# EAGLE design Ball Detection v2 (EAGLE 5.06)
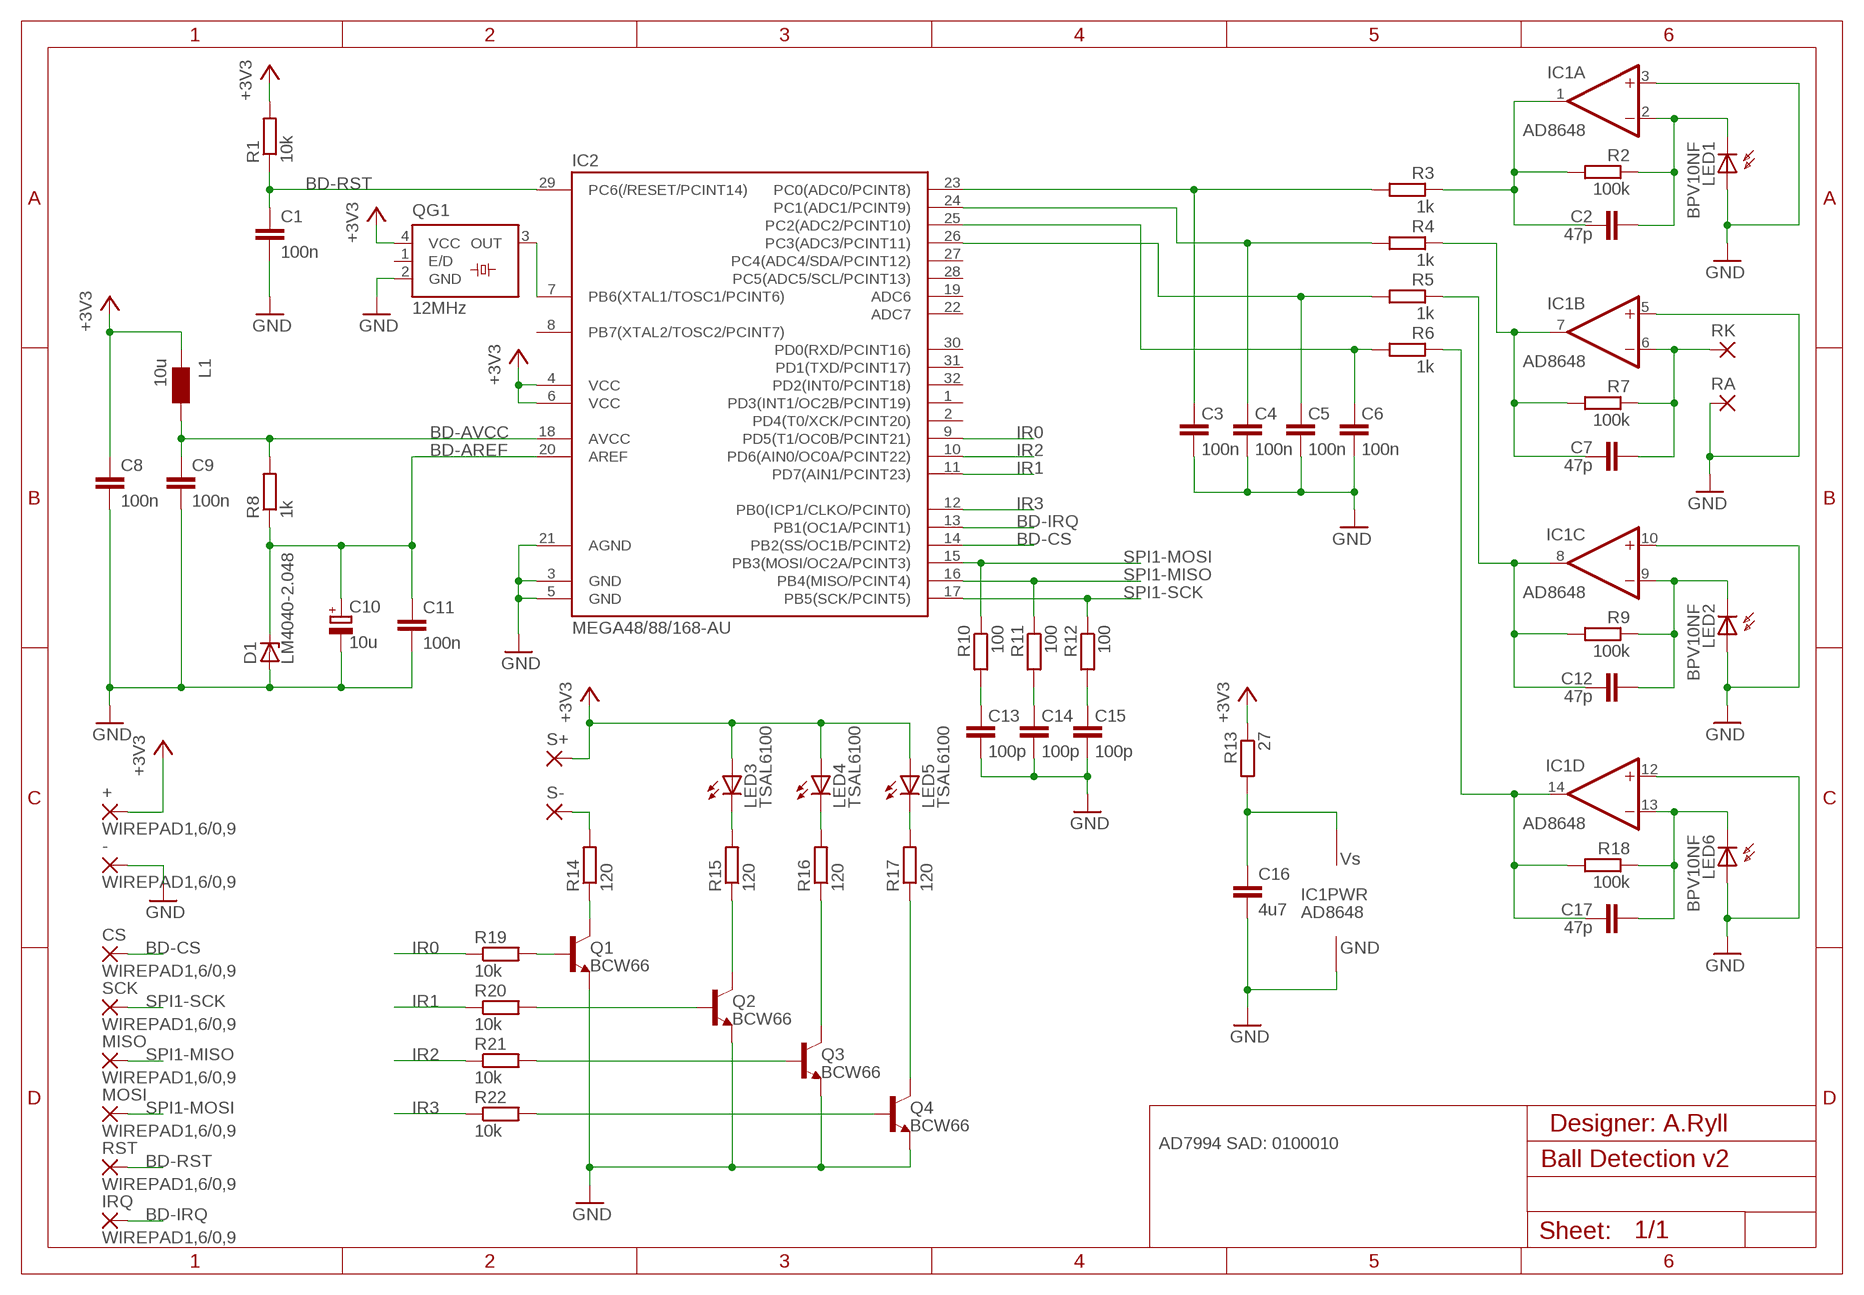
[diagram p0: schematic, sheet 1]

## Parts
+  WIREPAD1,6/0,9  [1,6/0,9]
-  WIREPAD1,6/0,9  [1,6/0,9]
C1  100n  C-EUC0805  [C0805]
C2  47p  C-EUC0805  [C0805]
C3  100n  C-EUC0805  [C0805]
C4  100n  C-EUC0805  [C0805]
C5  100n  C-EUC0805  [C0805]
C6  100n  C-EUC0805  [C0805]
C7  47p  C-EUC0805  [C0805]
C8  100n  C-EUC0805  [C0805]
C9  100n  C-EUC0805  [C0805]
C10  10u  CPOL-EUC/6032-28W  [C/6032-28W]
C11  100n  C-EUC0805  [C0805]
C12  47p  C-EUC0805  [C0805]
C13  100p  C-EUC0805  [C0805]
C14  100p  C-EUC0805  [C0805]
C15  100p  C-EUC0805  [C0805]
C16  4u7  C-EUC0805  [C0805]
C17  47p  C-EUC0805  [C0805]
CS  WIREPAD1,6/0,9  [1,6/0,9]
D1  LM4040-2.048  ZENER-DIODELM4040  [SOT23]
IC1  AD8648  [TSSOP14]
IC2  MEGA48/88/168-AU  [TQFP32-08]
IRQ  WIREPAD1,6/0,9  [1,6/0,9]
L1  10u  WE-MI_0805  [0805]
LED1  BPV10NF  PHOTO-LED  [LED5MM]
LED2  BPV10NF  PHOTO-LED  [LED5MM]
LED3  TSAL6100  LED5MM  [LED5MM]
LED4  TSAL6100  LED5MM  [LED5MM]
LED5  TSAL6100  LED5MM  [LED5MM]
LED6  BPV10NF  PHOTO-LED  [LED5MM]
MISO  WIREPAD1,6/0,9  [1,6/0,9]
MOSI  WIREPAD1,6/0,9  [1,6/0,9]
Q1  BCW66  BCW60SMD  [SOT23-BEC]
Q2  BCW66  BCW60SMD  [SOT23-BEC]
Q3  BCW66  BCW60SMD  [SOT23-BEC]
Q4  BCW66  BCW60SMD  [SOT23-BEC]
QG1  12MHz  SM77H  [SM77H]
R1  10k  R-EU_R0805  [R0805]
R2  100k  R-EU_R0805  [R0805]
R3  1k  R-EU_R0805  [R0805]
R4  1k  R-EU_R0805  [R0805]
R5  1k  R-EU_R0805  [R0805]
R6  1k  R-EU_R0805  [R0805]
R7  100k  R-EU_R0805  [R0805]
R8  1k  R-EU_R0805  [R0805]
R9  100k  R-EU_R0805  [R0805]
R10  100  R-EU_R0805  [R0805]
R11  100  R-EU_R0805  [R0805]
R12  100  R-EU_R0805  [R0805]
R13  27  R-EU_R0805  [R0805]
R14  120  R-EU_R0805  [R0805]
R15  120  R-EU_R0805  [R0805]
R16  120  R-EU_R0805  [R0805]
R17  120  R-EU_R0805  [R0805]
R18  100k  R-EU_R0805  [R0805]
R19  10k  R-EU_R0805  [R0805]
R20  10k  R-EU_R0805  [R0805]
R21  10k  R-EU_R0805  [R0805]
R22  10k  R-EU_R0805  [R0805]
RA  WIREPAD1,6/0,9  [1,6/0,9]
RK  WIREPAD1,6/0,9  [1,6/0,9]
RST  WIREPAD1,6/0,9  [1,6/0,9]
S+  WIREPAD1,6/0,9  [1,6/0,9]
S-  WIREPAD1,6/0,9  [1,6/0,9]
SCK  WIREPAD1,6/0,9  [1,6/0,9]

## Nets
+3V3: +.1(P) C8.1 IC2.4(VCC) IC2.6(VCC) L1.1 LED3.A LED4.A LED5.A QG1.4(VCC) R1.2 R13.1 S+.1(P)
AI0: C3.2 IC2.23(PC0(ADC0/PCINT8)) R3.2
AI1: C4.2 IC2.24(PC1(ADC1/PCINT9)) R4.2
AI2: C5.2 IC2.26(PC3(ADC3/PCINT11)) R5.2
AI3: C6.2 IC2.25(PC2(ADC2/PCINT10)) R6.2
BD-AREF: C10.+ C11.1 D1.1(C) IC2.20(AREF) R8.1
BD-AVCC: C9.1 IC2.18(AVCC) L1.2 R8.2
BD-CS: CS.1(P) IC2.14(PB2(SS/OC1B/PCINT2))
BD-IRQ: IC2.13(PB1(OC1A/PCINT1)) IRQ.1(P)
BD-RST: C1.1 IC2.29(PC6(/RESET/PCINT14)) R1.1 RST.1(P)
GND: -.1(P) C1.2 C3.1 C4.1 C5.1 C6.1 C8.2 C9.2 C10.- C11.2 C13.1 C14.1 C15.1 C16.2 D1.2(A) IC1.3(A:+IN) IC1.5(B:+IN) IC1.10(C:+IN) IC1.11(PWR:GND) IC1.12(D:+IN) IC2.3(GND) IC2.5(GND) IC2.21(AGND) LED1.A LED2.A LED6.A Q1.E Q2.E Q3.E Q4.E QG1.2(GND) RA.1(P)
IR0: IC2.9(PD5(T1/OC0B/PCINT21)) R19.1
IR1: IC2.11(PD7(AIN1/PCINT23)) R20.1
IR2: IC2.10(PD6(AIN0/OC0A/PCINT22)) R21.1
IR3: IC2.12(PB0(ICP1/CLKO/PCINT0)) R22.1
N$1: C2.2 IC1.1(A:OUT) R2.2 R3.1
N$2: C15.2 R12.2
N$3: C14.2 R11.2
N$4: C7.2 IC1.7(B:OUT) R4.1 R7.2
N$5: C12.2 IC1.8(C:OUT) R5.1 R9.2
N$6: C17.2 IC1.14(D:OUT) R6.1 R18.2
N$7: C13.2 R10.2
N$103: R14.2 S-.1(P)
N$104: LED3.K(C) R15.2
N$115: LED5.K(C) R17.2
N$116: LED4.K(C) R16.2
N$117: Q1.B R19.2
N$119: C2.1 IC1.2(A:-IN) LED1.K(C) R2.1
N$121: Q2.B R20.2
N$122: C7.1 IC1.6(B:-IN) R7.1 RK.1(P)
N$123: Q3.B R21.2
N$124: C12.1 IC1.9(C:-IN) LED2.K(C) R9.1
N$125: Q4.B R22.2
N$126: C17.1 IC1.13(D:-IN) LED6.K(C) R18.1
N$127: Q1.C R14.1
N$128: Q2.C R15.1
N$129: Q3.C R16.1
N$146: Q4.C R17.1
SPI1-MISO: IC2.16(PB4(MISO/PCINT4)) MISO.1(P) R11.1
SPI1-MOSI: IC2.15(PB3(MOSI/OC2A/PCINT3)) MOSI.1(P) R10.1
SPI1-SCK: IC2.17(PB5(SCK/PCINT5)) R12.1 SCK.1(P)
VOP: C16.1 IC1.4(PWR:VS) R13.2
XTAL: IC2.7(PB6(XTAL1/TOSC1/PCINT6)) QG1.3(OUT)
Unconnected: IC2.1(PD3(INT1/OC2B/PCINT19)) IC2.2(PD4(T0/XCK/PCINT20)) IC2.8(PB7(XTAL2/TOSC2/PCINT7)) IC2.19(ADC6) IC2.22(ADC7) IC2.27(PC4(ADC4/SDA/PCINT12)) IC2.28(PC5(ADC5/SCL/PCINT13)) IC2.30(PD0(RXD/PCINT16)) IC2.31(PD1(TXD/PCINT17)) IC2.32(PD2(INT0/PCINT18)) QG1.1(E/D)

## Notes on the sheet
- Designer: A.Ryll
- AD7994 SAD: 0100010

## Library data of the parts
+ - CS IRQ MISO MOSI RA RK RST S+ S- SCK = wirepad:WIREPAD: Wire PAD connect wire on PCB
C1-C9 C11-C17 = rcl:C-EU: CAPACITOR, European symbol
C10 = rcl:CPOL-EU: POLARIZED CAPACITOR, European symbol
D1 = Marvin:ZENER-DIODE: Z-Diode
IC1 = Marvin:AD8648
IC2 = avr-6:MEGA48/88/168
L1 = wuerth-elektronik:WE-MI: SMD Multilayer Inductor WE-MI
LED1 LED2 LED6 = Marvin:PHOTO-LED
LED3-LED5 = led:LED: LED
Q1-Q4 = transistor-npn:BCW60*: NPN Transistor
QG1 = crystal:SM77H: 3.3V CMOS Clock Oscillator Source: www.pletronics.com .. sm77h%203.3v.pdf
R1-R22 = rcl:R-EU_: RESISTOR, European symbol

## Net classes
0 default: width 0.152 mm, clearance 0.152 mm

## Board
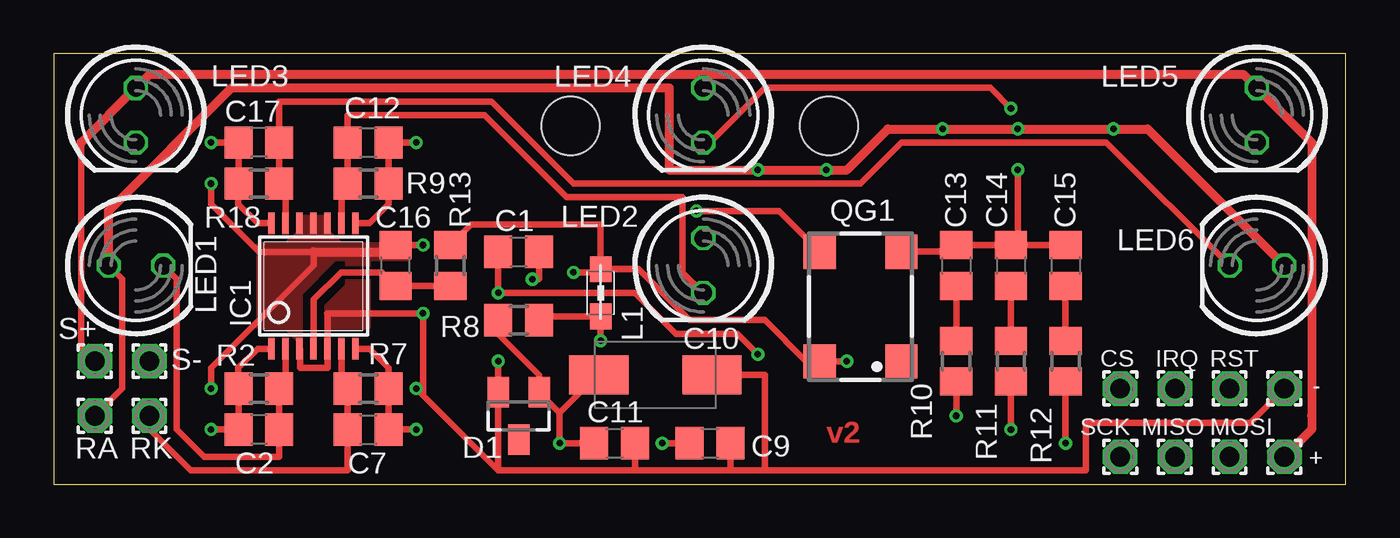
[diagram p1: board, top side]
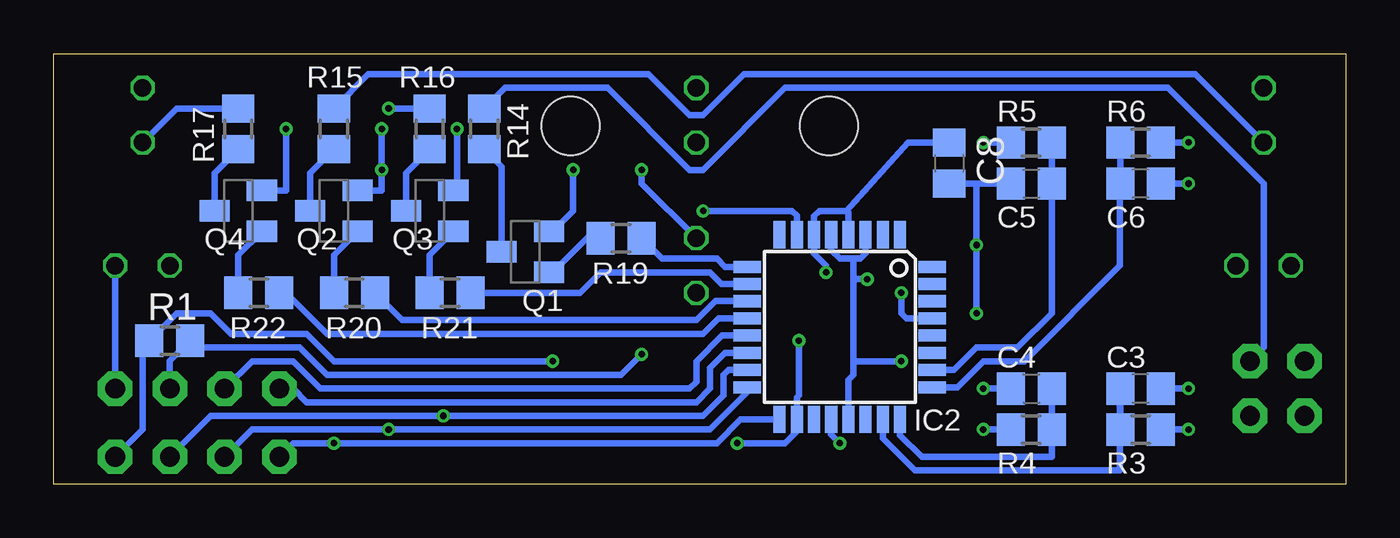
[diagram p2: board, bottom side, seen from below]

Size 60 x 20 mm. Coordinates in mm from the lower left corner, seen from the top.
Outline: 0,0 60,0 60,20 0,20 0,0
Copper layers (1*16): Top 0.035mm / dielectric 1.5mm / Bottom 0.035mm
Design rules "std *": minimum track width 10mil, minimum drill 0.3mm, track to track 0.15mm, track to pad 0.15mm, pad to pad 0.15mm, via to via 0.15mm, smd to smd 0.15mm, copper to edge 0.15mm, drill to drill 0.2mm, minimum pad ring 6mil, minimum via ring 6mil, stop-mask expansion 4mil, vias tented up to drill 0mil, thermal gap 10mil
Holes 2.7 mm at 24,16.65 36,16.65
bKeepout: area 21.6,12.7 to 38.1,19.7

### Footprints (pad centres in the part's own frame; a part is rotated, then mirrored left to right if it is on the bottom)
1,6/0,9 = drill 0.914 pad 1.6 octagon: 1 0,0
C0805 = smd 1.3 x 1.5: 1 -0.95,0; 2 0.95,0
C/6032-28W = smd 2.75 x 1.8: + 2.625,0; - -2.625,0
SOT23 = smd 1 x 1.4: 1 -0.95,-1.1; 2 0.95,-1.1; 3 0,1.1
TSSOP14 = smd 0.305 x 0.991: 1 -1.95,-2.918; 2 -1.3,-2.918; 3 -0.65,-2.918; 4 0,-2.918; 5 0.65,-2.918; 6 1.3,-2.918; 7 1.95,-2.918; 8 1.95,2.918; 9 1.3,2.918; 10 0.65,2.918; 11 0,2.918; 12 -0.65,2.918; 13 -1.3,2.918; 14 -1.95,2.918
TQFP32-08 = smd 1.27 x 0.559: 1 -4.293,2.8; 2 -4.293,2; 3 -4.293,1.2; 4 -4.293,0.4; 5 -4.293,-0.4; 6 -4.293,-1.2; 7 -4.293,-2; 8 -4.293,-2.8; 17 4.293,-2.8; 18 4.293,-2; 19 4.293,-1.2; 20 4.293,-0.4; 21 4.293,0.4; 22 4.293,1.2; 23 4.293,2; 24 4.293,2.8 | smd 0.559 x 1.27: 9 -2.8,-4.293; 10 -2,-4.293; 11 -1.2,-4.293; 12 -0.4,-4.293; 13 0.4,-4.293; 14 1.2,-4.293; 15 2,-4.293; 16 2.8,-4.293; 25 2.8,4.293; 26 2,4.293; 27 1.2,4.293; 28 0.4,4.293; 29 -0.4,4.293; 30 -1.2,4.293; 31 -2,4.293; 32 -2.8,4.293
0805 = smd 1.2 x 1: 1 -1.1,0; 2 1.1,0
LED5MM = drill 0.813 octagon: A -1.27,0; K 1.27,0
SOT23-BEC = smd 1 x 1.4: B -0.95,-1.1; C 0,1.1; E 0.95,-1.1
SM77H = smd 1.6 x 1.5: 1 -2.55,-1.9; 2 2.55,-1.9; 3 2.55,1.9; 4 -2.55,1.9
R0805 = smd 1.3 x 1.5: 1 -0.95,0; 2 0.95,0

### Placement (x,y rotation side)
+  57.15,1.27 0 top
-  57.15,4.45 0 top
C1  21.59,10.79 0 top
C2  9.53,2.54 180 top
C3  9.53,4.45 180 bottom
C4  14.61,4.45 0 bottom
C5  14.61,13.97 0 bottom
C6  9.53,13.97 180 bottom
C7  14.61,2.54 0 top
C8  18.41,14.92 270 bottom
C9  30.48,1.91 0 top
C10  27.94,5.08 180 top
C11  26.04,1.91 0 top
C12  14.61,15.88 0 top
C13  41.91,10.16 270 top
C14  44.45,10.16 270 top
C15  46.99,10.16 270 top
C16  15.88,10.16 90 top
C17  9.53,15.88 180 top
CS  49.53,4.45 0 top
D1  21.59,3.17 180 top
IC1  12.06,9.21 0 top
IC2  23.5,7.3 270 bottom
IRQ  52.07,4.45 0 top
L1  25.4,8.89 270 top
LED1  3.81,10.16 0 top
LED2  30.16,10.16 270 top
LED3  3.81,17.14 270 top
LED4  30.16,17.14 270 top
LED5  55.88,17.14 270 top
LED6  55.88,10.16 180 top
MISO  52.07,1.27 0 top
MOSI  54.61,1.27 0 top
Q1  38.1,10.79 90 bottom
Q2  46.99,12.7 90 bottom
Q3  42.55,12.7 90 bottom
Q4  51.44,12.7 90 bottom
QG1  37.47,8.26 90 top
R1  54.61,6.67 180 bottom
R2  9.53,4.45 180 top
R3  9.53,2.54 180 bottom
R4  14.61,2.54 0 bottom
R5  14.61,15.88 0 bottom
R6  9.53,15.88 180 bottom
R7  14.61,4.45 0 top
R8  21.59,7.62 0 top
R9  14.61,13.97 0 top
R10  41.91,5.71 90 top
R11  44.45,5.71 90 top
R12  46.99,5.71 90 top
R13  18.41,10.16 270 top
R14  40.01,16.51 90 bottom
R15  46.99,16.51 90 bottom
R16  42.55,16.51 90 bottom
R17  51.44,16.51 90 bottom
R18  9.53,13.97 180 top
R19  33.66,11.43 180 bottom
R20  46.04,8.89 180 bottom
R21  41.59,8.89 180 bottom
R22  50.48,8.89 180 bottom
RA  1.91,3.17 0 top
RK  4.45,3.17 0 top
RST  54.61,4.45 0 top
S+  1.91,5.71 0 top
S-  4.45,5.71 0 top
SCK  49.53,1.27 0 top

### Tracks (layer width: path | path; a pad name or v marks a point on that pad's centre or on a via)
+3V3  (via drill 0.3)
  Top 0.305: 1.27,15.88 1.27,6.35 S+.1 | v24.13,9.84 25.25,9.84 L1.1 | L1.1 25.4,12.06 19.37,12.06 R13.1 | L1.1 27.16,9.99 29.53,7.62 33.02,7.62 34.94,5.71 QG1.4 v36.83,5.71
  Top 0.406: 30.16,19.05 4.45,19.05 LED3.A 1.27,15.88 | 30.16,19.05 LED4.A | 30.16,19.05 55.24,19.05 LED5.A 58.42,15.88 58.42,3.17 58.42,2.54 +.1
  Bottom 0.305: IC2.4 23.09,12.62 23.18,12.7 | 23.18,12.7 24.45,12.7 24.7,12.45 IC2.6 24.7,10.72 24.13,10.16 v24.13,9.84 | C8.1 20.32,15.87 23.18,12.7 | +.1 55.88,2.54 55.88,6.67 55.56,6.99 R1.2 54.29,7.94 52.7,7.94 51.75,6.99 48.26,6.99 46.99,5.71 v36.83,5.71
AI0
  Bottom 0.305: R3.2 C3.2 10.48,0.64 20,0.64 21.5,2.13 IC2.23
AI1
  Bottom 0.305: C4.2 R4.2 13.65,1.27 19.68,1.27 20.7,2.28 IC2.24
AI2
  Bottom 0.305: R5.2 C5.2 13.65,7.94 15.24,6.35 17.14,6.35 18.19,5.3 IC2.26
AI3
  Bottom 0.305: R6.2 C6.2 10.48,10.16 14.92,5.71 16.83,5.71 18.04,4.5 IC2.25
BD-AREF  (via drill 0.3)
  Top 0.305: C11.1 v23.5,1.91 23.5,3.32 | 23.5,3.32 D1.1 22.54,5.08 20.64,6.98 R8.1 | C10.+ 25.25,5.08 23.5,3.32
  Bottom 0.305: IC2.20 23.89,2.31 v23.5,1.91
BD-AVCC  (via drill 0.3)
  Top 0.305: v28.26,1.91 C9.1 | v25.4,6.67 L1.2 22.71,7.79 R8.2
  Bottom 0.305: v28.26,1.91 26.04,1.91 25.5,2.44 IC2.18 25.5,4.03 25.4,4.13 v25.4,6.67
BD-CS
  Bottom 0.305: IC2.14 28.82,6.1 29.53,5.4 29.53,4.45 30.16,3.81 48.26,3.81 48.9,4.45 CS.1
BD-IRQ
  Bottom 0.305: IC2.13 28.98,6.9 30.16,5.71 30.16,4.76 30.48,4.45 47.62,4.45 48.9,5.71 50.8,5.71 IRQ.1
BD-RST  (via drill 0.3)
  Top 0.305: C1.1 v20.64,8.89 26.99,8.89 28.89,6.99 31.75,6.99 v32.7,6.03
  Bottom 0.305: RST.1 54.61,5.72 R1.1 53.66,6.35 48.58,6.35 47.31,5.08 33.66,5.08 v32.7,6.03 | IC2.29 20.4,7.7 20.64,7.94 v20.64,8.89
GND  (via drill 0.3)
  Top 0.305: v7.3,13.97 7.3,13.02 9.53,10.79 12.06,10.79 | 12.06,10.79 | v7.3,4.45 7.3,5.4 12.06,10.16 12.06,10.79 | 12.06,10.79 | IC1.3 11.43,6.28 11.43,5.4 12.7,5.4 12.71,5.41 IC1.5 12.71,7.92 12.7,7.94 v17.14,7.94 17.14,4.13 17.62,3.65 | RA.1 3.17,4.45 3.17,9.53 LED1.A | C14.1 C13.1 41.6,10.8 QG1.2 | C14.1 C15.1 | C14.1 44.77,11.43 44.77,14.29 v44.77,14.61 | 17.62,3.65 v16.83,4.45 | 17.62,3.65 20.64,0.64 20.95,0.64 | C16.2 v17.14,11.11 | v20.64,5.71 D1.2 20.64,0.64 20.95,0.64 | -.1 55.56,2.86 47.94,2.86 47.94,0.64 33.02,0.64 | 33.02,0.64 31.43,0.64 | 31.43,0.64 26.99,0.64 | 26.99,0.64 20.95,0.64 | C11.2 26.99,0.64 | C9.2 31.43,0.64 | C10.- 33.02,5.08 33.02,0.64 | C1.2 22.54,9.53 v22.23,9.53
  Top 0.406: LED6.A 50.8,16.51 v49.21,16.51 v44.77,16.51 v41.27,16.51 38.73,16.51 36.83,14.61 v35.88,14.61 v32.7,14.61 28.57,14.61 28.57,18.41 8.26,18.41 2.54,12.7 LED1.A | 12.06,10.79 16.19,10.79
  Bottom 0.305: Q3.E 41.28,13.65 v41.27,16.51 | Q2.E 44.77,13.65 v44.77,14.61 | v44.77,16.51 44.77,15.24 | 44.77,15.24 v44.77,14.61 | Q4.E 49.22,13.65 v49.21,16.51 | Q1.E 36.83,11.75 35.88,12.7 35.88,13.02 v35.88,14.61 | LED2.A 32.7,13.97 v32.7,14.61 | IC2.3 22.3,10.72 22.54,10.48 22.86,10.48 | 22.86,10.48 23.5,10.48 23.89,10.88 IC2.5 | IC2.21 23.09,4.84 22.86,5.08 22.86,5.71 | 22.86,5.71 22.86,9.53 | 22.86,9.53 22.86,10.48 | LED6.A -.1 | v44.77,14.61 44.77,15.24 | v16.83,4.45 C4.1 | v7.3,4.45 C3.1 | v7.3,13.97 C6.1 | 16.83,13.97 C5.1 | 16.83,13.97 C8.2 | 16.83,13.97 17.14,13.97 v17.14,11.11 v17.14,7.94 | v20.64,5.71 22.86,5.71 | 22.86,9.53 v22.23,9.53
  pour Top (no thermals): 16.51,11.11 13.34,11.11 12.7,11.75 12.7,12.38 11.43,12.38 11.43,11.75 10.79,11.11 9.53,11.11 9.53,7.3 10.79,7.3 11.43,6.67 11.43,8.89 13.02,10.48 16.51,10.48
  pour Top (no thermals): 13.65,10.48 13.65,9.21 12.7,8.26 12.7,7.3 14.61,7.3 14.61,10.48
IR0
  Bottom 0.305: IC2.9 28.84,10.1 29.21,10.48 31.75,10.48 R19.1
IR1
  Bottom 0.305: IC2.11 29.28,8.5 30.16,7.62 43.82,7.62 R20.1
IR2
  Bottom 0.305: IC2.10 28.99,9.3 29.53,9.84 34.61,9.84 35.56,8.89 R21.1
IR3
  Bottom 0.305: IC2.12 29.13,7.7 29.84,6.99 47.31,6.99 49.21,8.89 R22.1
N$1  (via drill 0.3)
  Top 0.305: IC1.1 9.46,6.29 8.57,5.4 R2.2 C2.2 | C2.2 v7.3,2.54 C2.2
  Bottom 0.305: v7.3,2.54 C2.2
N$2
  Top 0.305: R12.2 C15.2
N$3
  Top 0.305: R11.2 C14.2
N$4  (via drill 0.3)
  Top 0.305: IC1.7 14.66,6.29 15.56,5.4 R7.2 R4.1 v16.83,2.54
  Bottom 0.305: R4.1 v16.83,2.54
N$5  (via drill 0.3)
  Top 0.305: IC1.8 14.66,12.12 15.56,13.02 R9.2 R5.1 v16.83,15.88
  Bottom 0.305: v16.83,15.88 R5.1
N$6  (via drill 0.3)
  Top 0.305: IC1.14 9.46,12.12 8.57,13.02 R18.2 R6.1 v7.3,15.88
  Bottom 0.305: v7.3,15.88 R6.1
N$7
  Top 0.305: R10.2 C13.2
N$103
  Bottom 0.305: R14.2 39.05,18.41 34.29,18.41 30.48,14.61 29.84,14.61 26.04,18.41 8.26,18.41 3.81,13.97 3.81,6.35 S-.1
N$104
  Bottom 0.305: LED3.K 6.99,19.05 27.94,19.05 29.84,17.14 30.48,17.14 32.38,19.05 45.4,19.05 R15.2
N$115
  Bottom 0.305: LED5.K 54.3,17.46 R17.2
N$116  (via drill 0.3)
  Top 0.305: LED4.K 30.48,15.88 33.02,18.41 43.5,18.41 v44.45,17.46
  Bottom 0.305: v44.45,17.46 R16.2
N$117
  Bottom 0.305: Q1.B 36.83,9.85 35.24,11.43 R19.2
N$119
  Top 0.305: IC1.2 10.77,4.74 R2.1 C2.1 10.47,1.27 6.99,1.27 5.71,2.54 5.71,9.53 LED1.K
N$121
  Bottom 0.305: R20.2 46.99,10.65 Q2.B
N$122
  Top 0.305: IC1.6 13.37,4.74 R7.1 C7.1 13.65,0.64 6.35,0.64 4.45,2.54 RK.1
N$123
  Bottom 0.305: R21.2 42.55,10.65 Q3.B
N$124
  Top 0.305: IC1.9 13.37,13.68 R9.1 C12.1 13.65,17.14 20,17.14 23.81,13.34 29.21,13.34 29.21,9.84 LED2.K
N$125
  Bottom 0.305: R22.2 51.44,10.65 Q4.B
N$126
  Top 0.305: LED6.K 48.9,15.88 39.37,15.88 37.47,13.97 24.13,13.97 20.32,17.78 10.47,17.78 C17.1 R18.1 10.77,13.68 IC1.13
N$127
  Bottom 0.305: Q1.C 39.2,14.76 R14.1
N$128
  Bottom 0.305: Q2.C 48.09,14.46 R15.1
N$129
  Bottom 0.305: Q3.C 43.65,14.46 R16.1
N$146
  Bottom 0.305: Q4.C 52.53,14.46 R17.1
SPI1-MISO  (via drill 0.3)
  Top 0.305: v44.45,2.54 R11.1
  Bottom 0.305: IC2.16 27.79,4.28 29.53,2.54 v44.45,2.54 50.8,2.54 MISO.1
SPI1-MOSI  (via drill 0.3)
  Top 0.305: v41.91,3.17 R10.1
  Bottom 0.305: IC2.15 28.67,5.3 28.89,5.08 28.89,4.13 29.84,3.17 v41.91,3.17 52.7,3.17 MOSI.1
SPI1-SCK  (via drill 0.3)
  Top 0.305: v46.99,1.91 R12.1
  Bottom 0.305: IC2.17 28.11,3.01 29.21,1.91 v46.99,1.91 48.9,1.91 SCK.1
VOP
  Top 0.305: IC1.4 12.06,8.57 13.34,9.84 15.24,9.84 C16.1 16.19,9.21 17.78,9.21 R13.2
XTAL  (via drill 0.3)
  Top 0.305: v29.84,12.7 33.67,12.7 QG1.3
  Bottom 0.305: IC2.7 25.5,12.48 25.72,12.7 v29.84,12.7

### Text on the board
Top: v2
